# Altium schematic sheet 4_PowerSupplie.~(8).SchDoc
size 414 x 293 mm; SheetNumber: 4; SheetTotal: 4; PageSetup: Record=PageOptionsZCenterHorizontal=TrueZCenterVertical=TrueZPrintScale=1.00ZXCorrection=0.00ZYCorrection=0.00ZPrintKind=1ZBorderSize=5000000ZLeftOffset=0ZBottomOffset=0ZOrientation=2ZPaperLength=1000ZPaperWidth=1000ZScale=100ZPaperSource=7ZPrintQuality=-4ZMediaType=1ZDitherType=10ZPaperKind=A3ZPrintScaleMode=0; Razrabotal: {Разработал}; Proveril: {Проверил}; Tkontr: {Т.контр.}; Nkontr: {Н.контр.}; Ytverdil: {Утвердил}; Nazvanie1: {Название1}; Nazvanie2: {Название2}; Oboznachenie: {Обозначение}
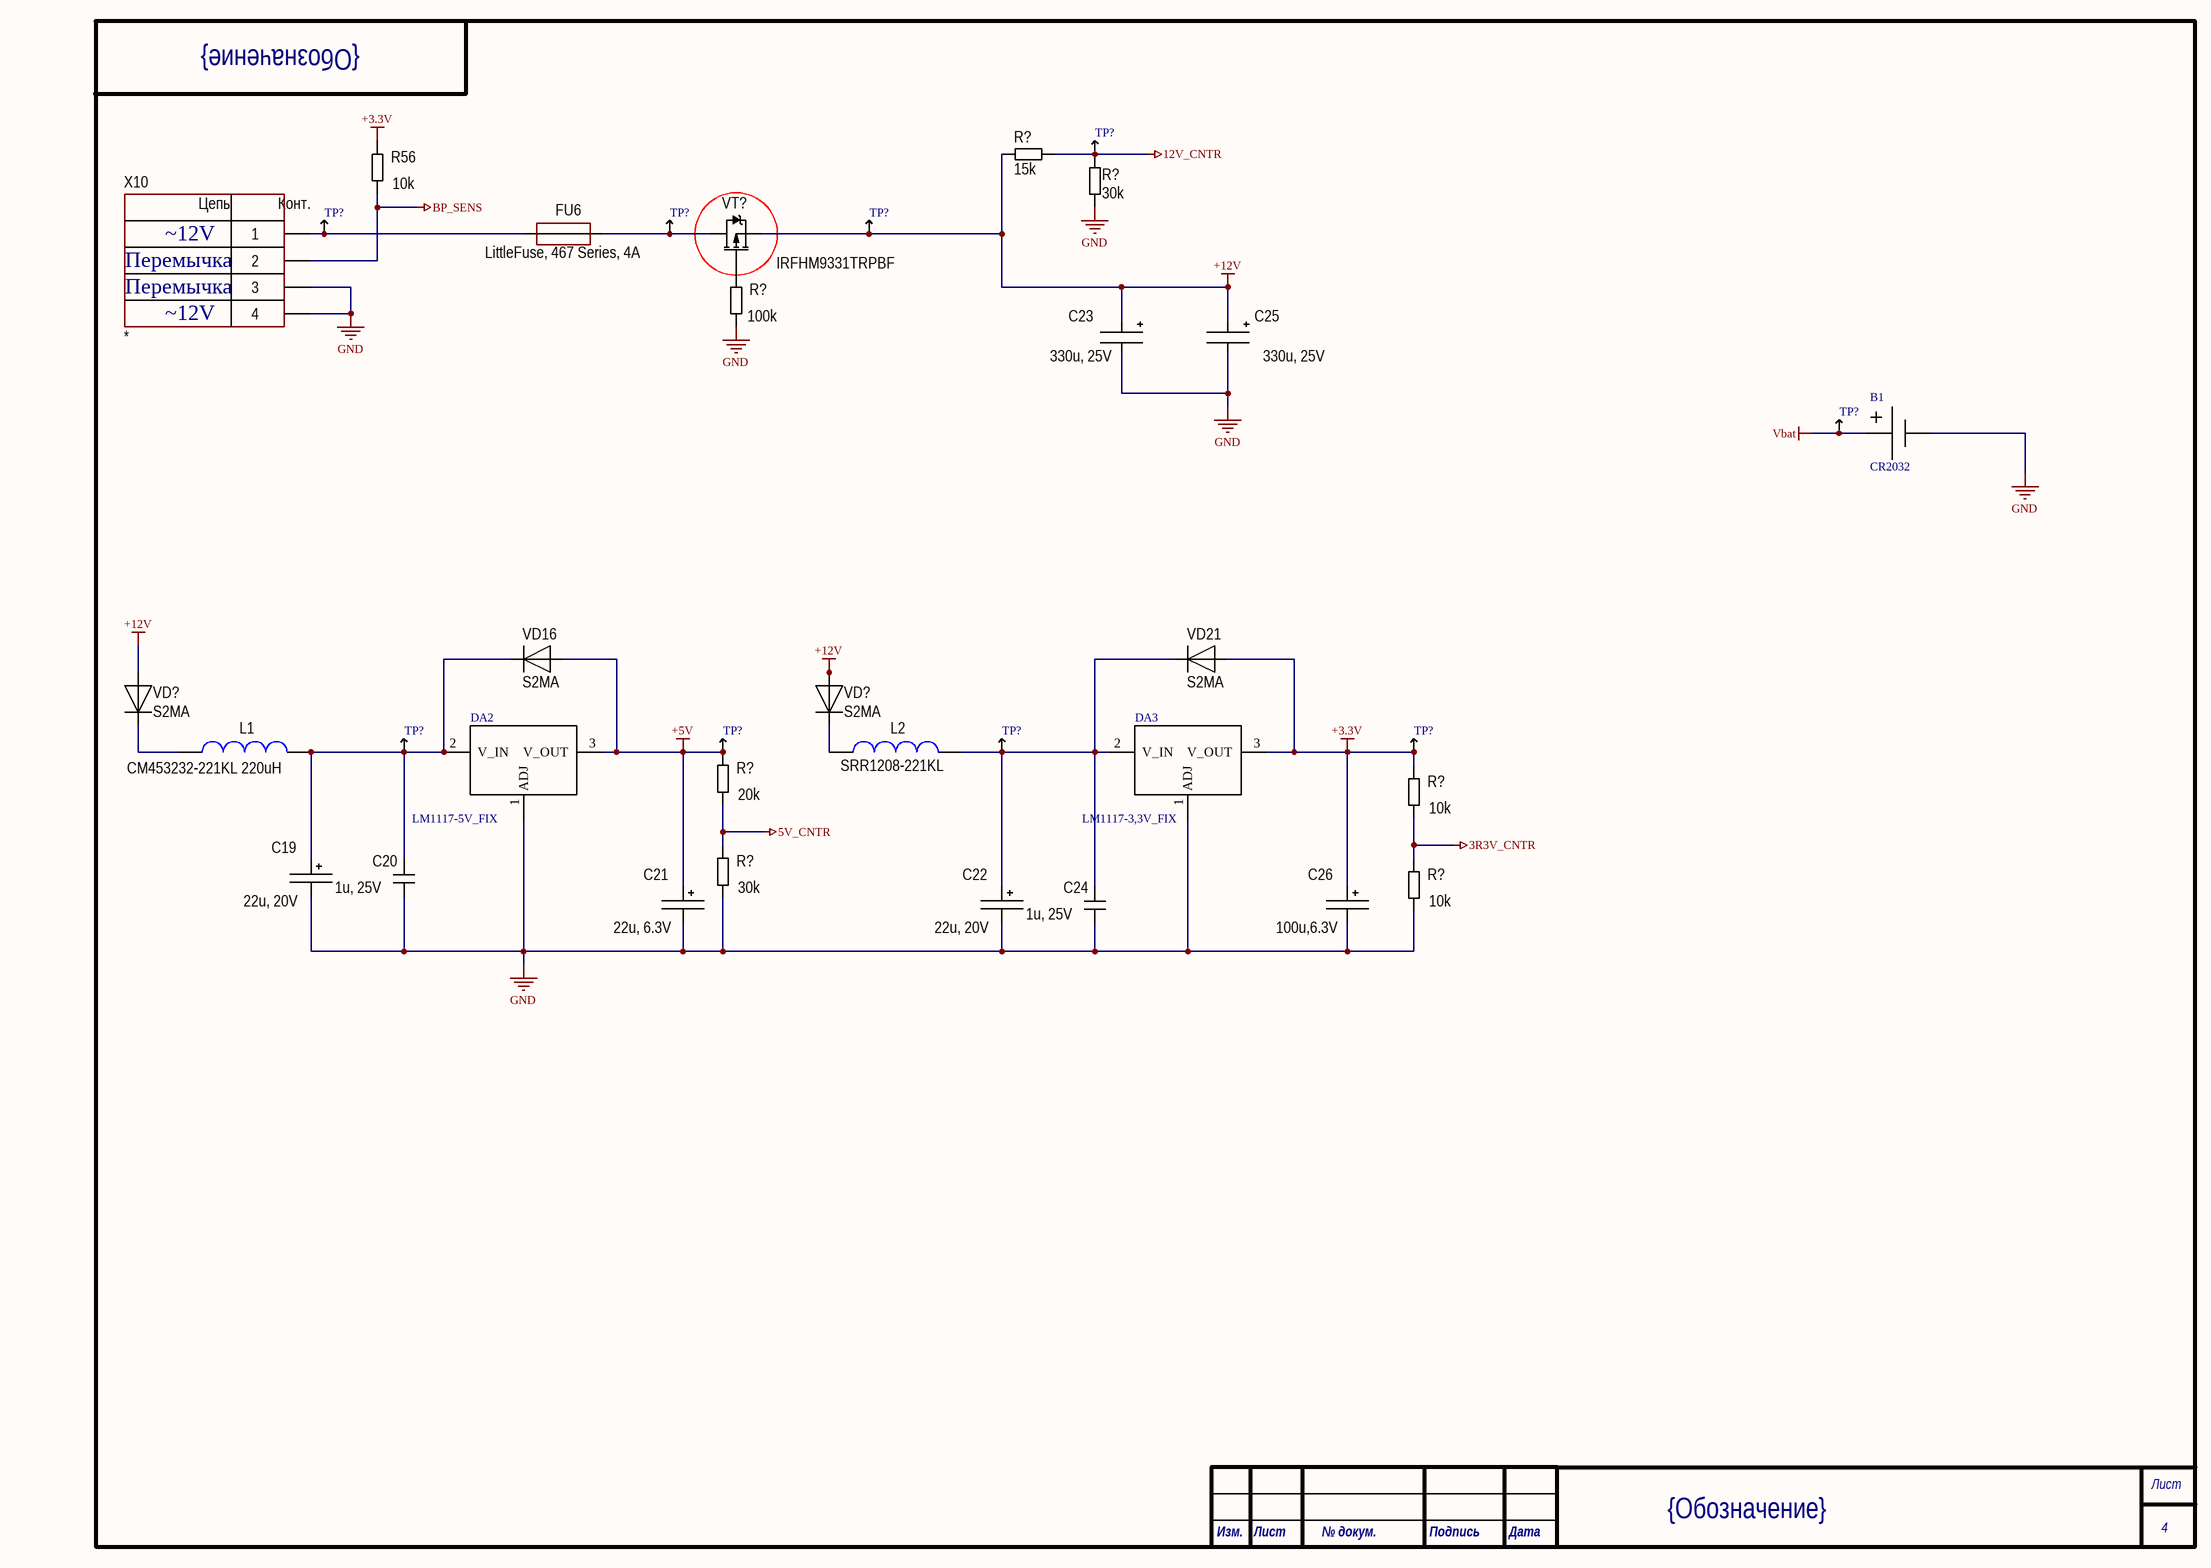
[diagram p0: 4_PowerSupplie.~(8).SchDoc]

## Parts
(Parts that share a designator on the sheet are numbered #1, #2 ... from top to bottom, then left to right.)
B1  CR2032  [CR2032]
C19  22u, 20V  [TANTAL_B]
C20  1u, 25V  [CH0805C]
C21  22u, 6.3V  [TANTAL_B]
C22  22u, 20V  [TANTAL_B]
C23  330u, 25V  [D10C4.4H10]
C24  1u, 25V  [CH0805C]
C25  330u, 25V  [D10C4.4H10]
C26  100u,6.3V  [TANTAL_B]
DA2  LM1117-5V_FIX  [SOT223_123]
DA3  LM1117-3,3V_FIX  [SOT223_123]
FU6  LittleFuse, 467 Series, 4A  [CH0603F]
L1  CM453232-221KL 220uH  [IND:1812]
L2  SRR1208-221KL  [IND: SRR1208]
R56  10k  [CH0805R]
R?#1  15k  [CH0805R]
R?#2  30k  [CH0805R]
R?#3  100k  [CH0805R]
R?#4  20k  [CH0805R]
R?#5  10k  [CH0805R]
R?#6  30k  [CH0805R]
R?#7  10k  [CH0805R]
TP?#1  TestPoint  (value not drawn)
TP?#2  TestPoint  (value not drawn)
TP?#3  TestPoint  (value not drawn)
TP?#4  TestPoint  (value not drawn)
TP?#5  TestPoint  (value not drawn)
TP?#6  TestPoint  (value not drawn)
TP?#7  TestPoint  (value not drawn)
TP?#8  TestPoint  (value not drawn)
TP?#9  TestPoint  (value not drawn)
VD16  S2MA  [SMA]
VD21  S2MA  [SMA]
VD?#1  S2MA  [SMA]
VD?#2  S2MA  [SMA]
VT?  IRFHM9331TRPBF  [SOT223]
X10  *  [CON: CWF-4]

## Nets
3R3V_CNTR: R?#5.1 R?#7.2
5V_CNTR: R?#4.1 R?#6.2
12V_CNTR: R?#1.1 R?#2.2 TP?#1.0
+3.3V: C26.1 DA3.3(V_OUT) R56.2 R?#5.2 TP?#9.0 VD21.1
+5V: C21.1 DA2.3(V_OUT) R?#4.2 TP?#7.0 VD16.1
+12V: C23.1 C25.1 R?#1.2 TP?#4.0 VD?#1.1 VD?#2.1 VT?.3(S)
BP_SENS: R56.1 X10.2
GND: B1.2 C19.2 C20.1 C21.2 C22.2 C23.2 C24.1 C25.2 C26.2 DA2.1(ADJ) DA3.1(ADJ) R?#2.1 R?#3.1 R?#6.1 R?#7.1 X10.3 X10.4
Vbat: B1.1 TP?#5.0
NetC19_1: C19.1 C20.2 DA2.2(V_IN) L1.1 TP?#6.0 VD16.2
NetC22_1: C22.1 C24.2 DA3.2(V_IN) L2.1 TP?#8.0 VD21.2
NetFU6_1: FU6.1 TP?#2.0 X10.1
NetFU6_2: FU6.2 TP?#3.0 VT?.2(D)
NetL1_2: L1.2 VD?#1.2
NetL2_2: L2.2 VD?#2.2
NetR?#3_2: R?#3.2 VT?.1(G)

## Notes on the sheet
- Перемычка
- 2V

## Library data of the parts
B1 = Battery_CR2032
C19 C21 C22 C26 = TantalCap
C20 C24 = Capacitor
C23 C25 = AlumCap
DA2 DA3 = LM1117
FU6 = Fuse
L1 L2 = Inductor
R56 R?#1-R?#7 = Resistor
VD16 VD21 VD?#1 VD?#2 = Diod
VT? = P-chanel: Mosfet
X10 = 4-Connector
